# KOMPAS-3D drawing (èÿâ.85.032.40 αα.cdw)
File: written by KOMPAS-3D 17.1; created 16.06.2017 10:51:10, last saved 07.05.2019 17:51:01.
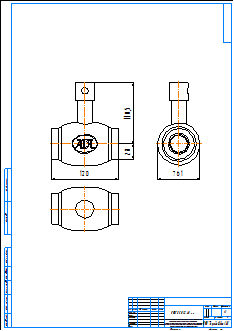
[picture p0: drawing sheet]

Sheet 1: A2, portrait

Title block, sheet 1: name: КШГ.85.032.40 рр; material: Внимание! Данный продукт является объектом авторского права ООО «Торговый Дом АДЛ». / Запрещается изменение, копирование, распространение / (в том числе путем копирования на другие сайты и ресурсы в Интернете) / или любое иное использование информации и объектов без предварительного / согласия правообладателя (ООО «Торговый Дом АДЛ»).; scale: 1:1; sheets: 1; organisation: ООО "Торговый дом АДЛ"; sheet format: A2; stored path: C:\Users\tra\Desktop\2д чертежи\Шаровые краны БИВАЛ\КШ_Бивал_серия_82_85\KOMPAS 2D\КШГ.85.032.40 рр.cdw

Views: Спереди 1, Проекционный вид 2, Проекционный вид 3
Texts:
  Klimkovich
  ADL
Dimensions and other numbers on the sheet: 120; 110,5; 28; 76,1; 1:1; 1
